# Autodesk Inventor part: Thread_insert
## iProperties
Shininess: 27.0
Length Units: 11269
Angle Units: 11279
Time Units: 11290
Mass Units: 11283
Length Display Precision: 3
Angle Display Precision: 2
Created: 2001-04
Part Number: Thread_insert
Material: Standard
Document SubType Name: Modellieren
Designer: dl
Density: 0.0
Volumn: 0.0
Area: 0.0
PropertySet Name: Model Information
Control State: 0
Master: False
Checked Out: False
Author: dl
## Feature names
1. Extrusion1
2. Hole1
